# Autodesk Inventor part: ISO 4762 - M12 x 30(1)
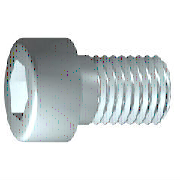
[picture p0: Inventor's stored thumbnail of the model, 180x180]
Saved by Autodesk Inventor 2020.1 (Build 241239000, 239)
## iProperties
Created: 2019-01
Part Number: ISO 4762 - M12 x 30(1)
Material: Edelstahl, 440C
Description: Innensechskantschraube
Document SubType Name: Modeling
Standard: ISO 4762
Designer: lutzd
Standard Revision: Fourth edition 2004-03-01
Standards Organization: ISO
Language: de-DE
Size Designation: M12 x 30
Categories: <MemberInstance><Categories><Category DisplayName="Verbindungselemente" InternalName="e4da775c-781d-43d5-af7c-5136215cf5a6" Mnemonic="FSTN"><Category DisplayNam
Mass: 44.7676 g
Surface Area: 24.9332 cm^2
Volume: 5.77647 cm^3
Density: 7.75 g/cm^3
Appearance: Halbpoliert
IsCustomPart: 0
Author: lutzd
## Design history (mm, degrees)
workplane "Work Plane1"
fillet "Fillet2" dims "d30" = 0.1 (= R)
sketch "Skizze1"
  geometry: L1 (-2.667, 0)-(30, 0); L2 (30, 0)-(30, 6); L3 (30, 6)-(4.375, 6); L4 (4.375, 6)-(3.301, 6); L5 (3.301, 6)-(0, 6); L6 (0, 6)-(0, 9); L7 (0, 9)-(-12, 9); L8 (-12, 9)-(-12, 5.774); L9 (-12, 5.774)-(-6, 5.774); L10 (-6, 5.774)-(-2.667, 0); L11 (-20.4, 0)-(38.4, 0) reference; L12 (0, -1.8)-(0, 10.8) reference; L13 (4.375, 6)-(0, 6)
  constraints: 22 end point, 6 parallel, 2 collinear, 2 perpendicular, 1 horizontal, 1 point on line
  dimensions: "d1" = 25.625 distance from line of L3.end L2 (= GEL); "d2" = 1.07364 distance of L4.end L3.end (computed from GAL); "d3" = 12 distance between parallel lines of L8 L6 (= KOH); "d4" = 6 distance of L8.end L9.end (= INTI); "d5" = 60 deg angle of L10 L1; "d6" = 12 diameter of L3 L1 (= GD); "d7" = 12 diameter of L5 L1 (= BDM); "d8" = 11.54701 diameter of L9 L1 (= 1.1547 x SW); "d9" = 18 diameter of L7 L1 (= KOD); "d26" = 30 distance between parallel lines of L12 L2 (= NLG)
revolve "Körper" sketch "Skizze1" stored, may be unused: angle "d10" = 90 deg
sketch "Skizze2"
  geometry: L1 (0, -12.6)-(0, 12.6) reference; L2 (-12.6, 0)-(12.6, 0) reference; L3 (5.774, 0)-(2.887, -5); L4 (2.887, -5)-(-2.887, -5); L5 (-2.887, -5)-(-5.774, 0); L6 (-5.774, 0)-(-2.887, 5); L7 (-2.887, 5)-(2.887, 5); L8 (2.887, 5)-(5.774, 0); 2 further points
  constraints: 12 end point, 1 coincident, 1 horizontal alignment, 1 point on line, 12 other
extrude "Loch" join sketch "Skizze2" stored distance "d11" = 10; taper "d12" = 0 deg
body "Solid1"
fillet "Rundung1" dims "d17" = 1.2 (= RR)
feature "Gewinde" dims "d13" = 25.625 (= GEL), "d14" = 0
chamfer "Fase1" distance "d15" = 1.07354 (= -0.5 x SPD + 0.5 x GD); stored, may be unused: second distance "d16" = 1.07354 (= GUL), angle "d27" = 45 deg
other parameters: "GD" = 12 [user parameter; used in 2 equation terms], "NLG" = 30 [user parameter; used in 1 equation term], "GEL" = 25.625 [user parameter; used in 2 equation terms], "KOD" = 18 [user parameter; used in 1 equation term], "KOH" = 12 [user parameter; used in 1 equation term], "INTI" = 6 [user parameter; used in 1 equation term], "GAL" = 1.07354 (= 0.61345 x PTC) [user parameter; used in 1 equation term], "GUL" = 1.07354 (= 0.61345 x PTC) [user parameter; used in 1 equation term], "BDM" = 12 (= NND) [user parameter; used in 1 equation term], "RR" = 1.2 [user parameter; used in 1 equation term], "SPD" = 9.85293 (= NND - 1.2269 x PTC) [user parameter; used in 1 equation term], "d19" = 0, "d28" = 0, "d29" = 0, "R" = 0.1 [user parameter; used in 1 equation term], "TOA" = 30 deg [user parameter], "GD1" = 9.85293 (= THREADDIA - 1.2269 x PTC) [user parameter], "THREADDIA" = 12 [user parameter; used in 1 equation term], "FAWI" = 45 deg [user parameter], "TPU" = 5.71429 (computed from PTC) [user parameter], "PTC" = 1.75 [user parameter; used in 5 equation terms], "NND" = 12 [user parameter; used in 2 equation terms], "E0" = 11.55 (= 1.155 x SW) [user parameter]
